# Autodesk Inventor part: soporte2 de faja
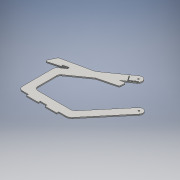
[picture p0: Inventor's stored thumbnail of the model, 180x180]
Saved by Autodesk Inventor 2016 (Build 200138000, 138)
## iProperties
Created: 2016-06
Part Number: soporte2 de faja
Material: Genérico
Document SubType Name: Modeling
Designer: adm
Density: 1 g/cm^3
Appearance: Valor por defecto
Author: adm
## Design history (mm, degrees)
sketch "Boceto1"
  geometry: L1 (-172.816, -58.403)-(-70.881, 13.642); L2 (-99.407, 42.463)-(-226.174, 14.411); L3 (-99.407, 42.463)-(-253.277, 8.414); L4 (-201.273, -230.979)-(-169.73, -230.979); L5 (-181.273, -74.736)-(-181.273, -170.979); L6 (-221.273, -54.025)-(-221.273, -210.979); L7 (-181.273, -15.398)-(-212.816, -37.692); L8 (-211.978, -14.169)-(-210.451, -19.972); L9 (-183.373, -12.849)-(-210.451, -19.972); L10 (-183.373, -12.849)-(-184.899, -7.046); L11 (-211.978, -14.169)-(-184.899, -7.046); L12 (-184.899, -7.046)-(-211.978, -14.169); L13 (-210.451, -19.972)-(-183.373, -12.849); L14 (-269.159, -38.518)-(-181.273, -15.398); L15 (-256.687, 5.732)-(-274.921, -31.482); L16 (23.163, 83.783)-(25.612, 85.514); L17 (25.612, 85.514)-(23.163, 83.783); L18 (25.514, 89.119)-(27.246, 86.669); L19 (25.514, 89.119)-(27.246, 86.669); L20 (32.022, 90.045)-(27.246, 86.669); L21 (55.109, 102.688)-(28.977, 84.219); L22 (27.246, 86.669)-(55.828, 106.87); L23 (22.169, 69.365)-(1.485, 64.788); L24 (22.169, 69.365)-(1.485, 64.788); L25 (25.514, 89.119)-(54.096, 109.32); L26 (1.485, 64.788)-(55.109, 102.688); L27 (8.297, 110.013)-(25.612, 85.514); L28 (5.847, 108.282)-(23.163, 83.783); L29 (8.297, 110.013)-(5.847, 108.282); L30 (-15.003, -240.979)-(-15.003, -230.979); L31 (-15.003, -240.979)-(-15.003, -230.979); L32 (-15.003, -230.979)-(22.302, -230.979); L33 (201.715, -33.835)-(45.284, -220.263); L34 (45.284, -220.263)-(201.715, -33.835); L35 (171.073, -8.123)-(26.631, -180.263); L36 (54.096, 109.32)-(55.828, 106.87); L37 (57.428, 104.605)-(57.559, 104.42); L38 (-70.881, 13.642)-(22.812, 38.289); L39 (-70.881, 13.642)-(22.812, 38.289); L40 (32.022, 135.353)-(-99.407, 42.463); L41 (32.022, 135.353)-(-99.407, 42.463); L42 (26.532, 42.84)-(27.743, 64.115); L43 (26.532, 42.84)-(27.743, 64.115); L44 (-169.73, -230.979)-(-169.73, -240.979); L45 (-169.73, -230.979)-(-169.73, -240.979); L46 (-169.73, -230.979)-(-169.73, -240.979); L47 (-169.73, -240.979)-(-109.73, -240.979); L48 (-169.73, -240.979)-(-109.73, -240.979); L49 (-109.73, -240.979)-(-109.73, -230.979); L50 (-109.73, -240.979)-(-109.73, -230.979); L51 (-109.73, -240.979)-(-109.73, -230.979); L52 (-109.73, -230.979)-(-75.003, -230.979); L53 (-109.73, -230.979)-(-75.003, -230.979); L54 (-75.003, -230.979)-(-75.003, -240.979); L55 (-75.003, -230.979)-(-75.003, -240.979); L56 (-161.273, -190.979)-(3.65, -190.979); L57 (-75.003, -240.979)-(-15.003, -240.979); L58 (-75.003, -240.979)-(-15.003, -240.979); C1 r 3.25 at (186.394, -20.979); C2 r 3.75 at (186.394, -20.979); C3 r 3.75 at (43.566, 119.021); A1 r 20 centre (-161.273, -74.736) between (-172.816, -58.403) and (-181.273, -74.736); A2 r 20 centre (-161.273, -170.979) between (-181.273, -170.979) and (-161.273, -190.979); A3 r 20 centre (-201.273, -210.979) between (-221.273, -210.979) and (-201.273, -230.979); A4 r 20 centre (-201.273, -54.025) between (-212.816, -37.692) and (-221.273, -54.025); A5 r 5 centre (-252.197, 3.532) between (-253.277, 8.414) and (-256.687, 5.732); A6 r 5 centre (-270.431, -33.682) between (-274.921, -31.482) and (-269.159, -38.518); A7 r 30 centre (3.65, -160.979) between (3.65, -190.979) and (26.631, -180.263); A8 r 30 centre (3.65, -160.979) between (3.65, -190.979) and (26.631, -180.263); A9 r 30 centre (22.302, -200.979) between (22.302, -230.979) and (45.284, -220.263); A10 r 30 centre (22.302, -200.979) between (22.302, -230.979) and (45.284, -220.263); A11 r 20 centre (186.394, -20.979) between (201.715, -33.835) and (171.073, -8.123); A12 r 20 centre (43.566, 119.021) between (55.109, 102.688) and (32.022, 135.353); A13 r 5 centre (22.751, 64.399) between (27.743, 64.115) and (22.169, 69.365); A14 r 5 centre (22.751, 64.399) between (27.743, 64.115) and (21.183, 69.147); A15 r 5 centre (21.54, 43.125) between (22.812, 38.289) and (26.532, 42.84); A16 r 5 centre (21.54, 43.125) between (22.812, 38.289) and (26.532, 42.84); 8 further points
  constraints: 119 end point, 36 point on circle, 19 centre point, 14 point on line, 14 tangent, 10 parallel, 7 coincident, 7 collinear, 6 perpendicular, 3 vertical, 2 horizontal
  dimensions: "d0" = 40 distance between parallel lines of L5 L6; "d1" = 20 radius of A2; "d2" = 20 radius of A3; "d3" = 20 radius of A1; "d4" = 20 radius of A4; "d5" = 7.5 diameter of C2; "d6" = 160 distance of L2.start point (-255.628, 7.894); "d7" = 7.5 diameter of C3; "d8" = 5 radius of A5; "d9" = 5 radius of A6; "d10" = 10 distance between parallel lines of L47 L4; "d11" = 10 distance between parallel lines of L52 L57; "d12" = 3 distance between parallel lines of L27 L28; "d13" = 2 distance between parallel lines of L27 L18
extrude "Extrusión1" new body sketch "Boceto1" distance "d14" = 6; taper "d15" = 0 deg
node "Sólido1"
